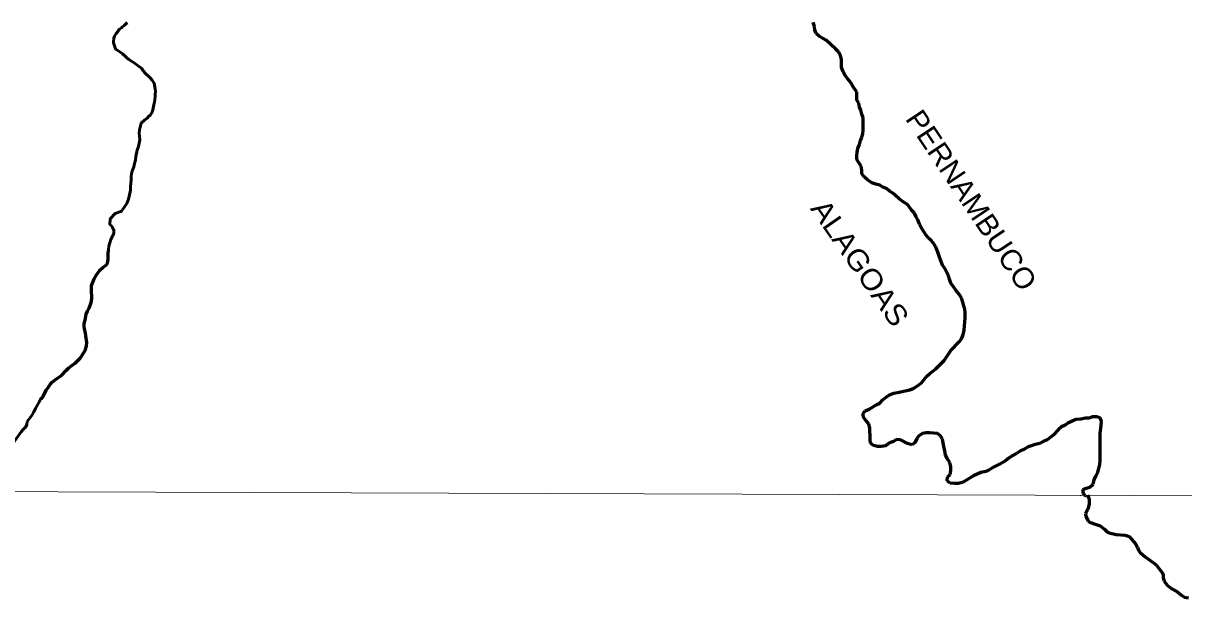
# Model space of a CAD drawing. Extents: x 553962 to 842807, y 8883888 to 9032388.
# Drawn here: x 626649 to 648955, y 9002899 to 9013939 of the extents above; entities that cross this region are included whole.
import ezdxf
from ezdxf.enums import TextEntityAlignment as Align

# ---------------------------------------------------------------- set-up
doc = ezdxf.new("R2010")
doc.units = 0
doc.header["$LTSCALE"] = 150
doc.linetypes.add('LONG_DASH_SHORT_DASH', pattern=[9.9, 6, -1.2, 1.5, -1.2])
for name, color, linetype, lineweight in [('1', 7, 'Continuous', 13), ('24', 7, 'Continuous', 25), ('7', 7, 'LONG_DASH_SHORT_DASH', 60)]:
    doc.layers.add(name, color=color, linetype=linetype, lineweight=lineweight)
doc.layers.add('42', color=7, linetype='Continuous')

msp = doc.modelspace()

# ---------------------------------------------------------------- linework, layer by layer
at = {"layer": '1'}
msp.add_lwpolyline([(565303.2, 9005146.6), (664889.8, 9004806.7), (719872.1, 9004543.9), (790635.8, 9004109)], dxfattribs=at)
for points in [[(646965.9, 9004860.1), (647054.2, 9004901.6), (647053.5, 9004901.6), (647052.8, 9004897.4), (647051.4, 9004891.8), (647051.4, 9004880.6), (647051.4, 9004873.6), (647051.4, 9004869.4), (647051.4, 9004865.2), (647051.4, 9004859.6), (647052.1, 9004852.6), (647052.1, 9004847), (647052.1, 9004842.8), (647052.1, 9004842.1), (647052.1, 9004841.4), (647052.1, 9004840.7), (647052.8, 9004840.7), (647053.5, 9004840.7), (647057.7, 9004841.4), (647061.9, 9004842.1), (647068.9, 9004842.8), (647077.3, 9004843.5), (647085.7, 9004847.7), (647091.3, 9004849.1), (647099.7, 9004853.3), (647109.5, 9004854), (647116.5, 9004858.2), (647123.5, 9004862.4), (647124.9, 9004863.8), (647124.9, 9004868), (647124.9, 9004869.4), (647124.9, 9004870.8), (647124.9, 9004871.5), (647124.9, 9004872.9), (647124.9, 9004874.3), (647124.9, 9004875), (647124.9, 9004875.7), (647124.2, 9004875), (647122.8, 9004873.6), (647122.1, 9004865.2), (647120.7, 9004858.2), (647120, 9004854), (647120, 9004854.7), (647120, 9004855.4), (647120, 9004859.6), (647120, 9004861), (647121.4, 9004862.4), (647122.1, 9004866.6), (647122.1, 9004870.8), (647122.8, 9004876.4), (647122.8, 9004877.8), (647123.5, 9004877.8), (647124.2, 9004877.8), (647124.9, 9004877.8), (647125.6, 9004877.8)], [(647125.6, 9004877.8), (647126.3, 9004877.8), (647125.6, 9004877.8), (647126.3, 9004877.8)]]:
    msp.add_spline(points, degree=3, dxfattribs=at)
at = {"layer": '24', "lineweight": 53}
for points in [[(628385.1, 9013563.7), (628384.6, 9013589.1), (628393.8, 9013653.1), (628406.8, 9013693.5), (628435.3, 9013742.5), (628473.3, 9013786.9), (628489.7, 9013813.2), (628501.5, 9013824.6), (628538.5, 9013852.9), (628556, 9013869.9), (628589.9, 9013894.5), (628628.8, 9013933.2), (628651.1, 9013946.4)], [(628991.5, 9012087.3), (629022.5, 9012108.1), (629071.7, 9012160), (629084.9, 9012162.8), (629086.9, 9012173.2), (629118.1, 9012217.5), (629138.3, 9012273), (629162, 9012369), (629172, 9012423.6), (629184.2, 9012523.3), (629184.4, 9012576), (629190.2, 9012625.9), (629183.6, 9012680.4), (629167.1, 9012786.6), (629159.2, 9012796.9), (629128.4, 9012844.8), (629090.7, 9012887.9), (628980.3, 9012992.9), (628979, 9013000.4), (628970.9, 9013002.3), (628969.2, 9013017.3), (628950.2, 9013031.4), (628929.8, 9013068.9), (628829.8, 9013142.9), (628780.7, 9013176.6), (628727.8, 9013209.3), (628680.6, 9013243), (628636, 9013283.3), (628574.8, 9013335.8), (628552.3, 9013351.7), (628548.7, 9013360.1), (628427, 9013439.7), (628422.5, 9013448.1), (628385.1, 9013563.7)], [(626725, 9006288.4), (626779.1, 9006348.8), (626820, 9006414.7), (626852.1, 9006473.1), (626884.2, 9006537.2), (626914.5, 9006591.8), (626995.8, 9006730.4), (627000.8, 9006736), (627018.2, 9006741.7), (627022, 9006744.6), (627030, 9006769), (627091.7, 9006889.6), (627130.8, 9006942.4), (627168.5, 9006999), (627205.7, 9007042.3), (627264.5, 9007088.6), (627330, 9007129.3), (627383.4, 9007169.9), (627473.6, 9007266.1), (627521.8, 9007311.4), (627580.8, 9007360.5), (627647.4, 9007407.8), (627691, 9007452.1), (627741.2, 9007505), (627838.2, 9007649.2), (627862.8, 9007736.7), (627868.9, 9007802.6), (627855.6, 9007930.4), (627843.1, 9007991.5), (627825.9, 9008062.9), (627820.1, 9008114.6), (627823, 9008171.1), (627839.1, 9008232.2), (627861.6, 9008347.1), (627883.5, 9008403.6), (627919.6, 9008464.8), (627956.3, 9008575), (627969.5, 9008644.6), (627969.3, 9008703.9), (627962.7, 9008772.5), (627963, 9008898.5), (627984.8, 9008964.4), (628013.5, 9009025.6), (628060.6, 9009104.8), (628119, 9009194.3), (628125.3, 9009200.9), (628181.5, 9009242.5), (628249.4, 9009298.2), (628267.2, 9009335.9), (628279.4, 9009398.9), (628279.5, 9009462.9), (628282.4, 9009525), (628295.3, 9009656.7), (628310.9, 9009719.8), (628332.7, 9009781.9), (628390, 9009900.6), (628393.8, 9009911.9), (628393.7, 9009960.8), (628392.5, 9009967.4), (628378, 9009983.3), (628365.8, 9010017.1), (628342.8, 9010045.3), (628316.9, 9010072.4), (628323, 9010177.8), (628415.6, 9010283.4), (628526.3, 9010323.3), (628535.7, 9010328), (628642.2, 9010476), (628665.7, 9010541), (628685.1, 9010606.9), (628709.8, 9010732.1), (628710.2, 9010799.8), (628722.3, 9010925.8), (628722.4, 9010990.7), (628731.8, 9011054.7), (628747.3, 9011116.8), (628773, 9011182.8), (628789.2, 9011246.8), (628807.6, 9011309.8), (628814.8, 9011376.6), (628839.2, 9011499.9), (628862, 9011567.7), (628878.5, 9011635.5), (628887.4, 9011699.5), (628887.1, 9011760.6), (628880.7, 9011826.4), (628881.1, 9011890.3), (628917.2, 9012018.4), (628991.5, 9012087.3)], [(626161, 9005249.2), (626188.6, 9005351.8), (626211.6, 9005488.2), (626262, 9005622), (626290.8, 9005686), (626318.1, 9005740.6), (626357.2, 9005784), (626440.5, 9005861.4), (626481.1, 9005905.8), (626516.3, 9005951), (626547.5, 9005998.1), (626576.5, 9006046.2), (626606.6, 9006087.7), (626651.3, 9006133.9), (626697.2, 9006185.8), (626721.1, 9006227.2), (626725, 9006288.4)]]:
    msp.add_lwpolyline(points, dxfattribs=at)
at = {"layer": '7'}
for points in [[(642587.9, 9012738.2), (642555, 9012803.3), (642491.9, 9012875.8), (642449, 9012935.9), (642411, 9013003.5), (642378, 9013091.2), (642377.5, 9013241.9), (642359.6, 9013319.6), (642321.7, 9013387.2), (642261.2, 9013447.2), (642084.7, 9013614.7), (642014.2, 9013649.5), (641953.8, 9013686.9), (641888.2, 9013741.9), (641865.4, 9013807), (641855.1, 9013874.8), (641829.7, 9013952.5)], [(642956.5, 9010871.9), (642875.9, 9010931.8), (642812.9, 9010989.2), (642767.5, 9011046.8), (642764.7, 9011117.1), (642756.9, 9011189.8), (642714, 9011252.4), (642671, 9011320), (642668.2, 9011392.8), (642675.5, 9011460.6), (642692.8, 9011531), (642720.2, 9011611.5), (642740, 9011684.4), (642767.4, 9011749.8), (642787.2, 9011815.1), (642792, 9011885.4), (642791.1, 9012118.9), (642768.3, 9012191.6), (642750.4, 9012266.9), (642720, 9012329.5), (642709.7, 9012402.3), (642674.3, 9012462.4), (642669, 9012537.7), (642668.7, 9012615.5), (642587.9, 9012738.2)], [(642909.8, 9006525.4), (642972.5, 9006563.4), (643042.7, 9006603.9), (643110.4, 9006636.8), (643173, 9006699.9), (643233.1, 9006755.4), (643300.8, 9006800.9), (643383.6, 9006828.9), (643451.3, 9006846.8), (643689.8, 9006898), (643767.6, 9006926), (643840.3, 9006969), (643907.9, 9007024.6), (643960.5, 9007085.1), (644013, 9007153.1), (644073.1, 9007208.6), (644128.2, 9007249), (644188.3, 9007299.5), (644348.5, 9007460.9), (644480.9, 9007652.3), (644638.6, 9007816.2), (644681, 9007874.2), (644715.9, 9007949.6), (644735.7, 9008040.1), (644740.4, 9008123), (644752.4, 9008281.2), (644752, 9008371.6), (644749.2, 9008446.9), (644726.4, 9008512.1), (644706.1, 9008577.3), (644685.6, 9008662.5), (644630.1, 9008742.6), (644574.6, 9008810.2), (644531.6, 9008875.3), (644478.6, 9008945.3), (644453.2, 9009020.6), (644432.8, 9009088.2), (644394.9, 9009160.9), (644364.5, 9009226), (644319, 9009288.6), (644283.6, 9009373.8), (644253.1, 9009461.5), (644230.2, 9009539.3), (644192.1, 9009634.5), (644149.2, 9009702.1), (644098.7, 9009762.2), (644045.8, 9009812.1), (643997.8, 9009874.7), (643906.8, 9010017.4), (643876.5, 9010080), (643846, 9010160.2), (643810.6, 9010220.3), (643780.2, 9010290.5), (643729.8, 9010343), (643646.4, 9010458.1), (643563.3, 9010510.5), (643485.3, 9010562.9), (643417.2, 9010627.8), (643364.3, 9010672.8), (643296.3, 9010710.2), (643238.3, 9010762.6), (643170.4, 9010790), (643112.5, 9010829.9), (643034.5, 9010844.6), (642956.5, 9010871.9)], [(626960, 9006669.3), (626995.8, 9006730.4), (627000.8, 9006736), (627018.2, 9006741.7), (627022, 9006744.6), (627030, 9006769), (627091.7, 9006889.6), (627130.8, 9006942.4), (627168.5, 9006999), (627205.7, 9007042.3), (627264.5, 9007088.6), (627330, 9007129.3), (627383.4, 9007169.9), (627473.6, 9007266.1), (627521.8, 9007311.4), (627580.8, 9007360.5), (627647.4, 9007407.8), (627691, 9007452.1), (627741.2, 9007505), (627838.2, 9007649.2), (627862.8, 9007736.7), (627868.9, 9007802.6), (627855.6, 9007930.4), (627843.1, 9007991.5), (627825.9, 9008062.9), (627820.1, 9008114.6), (627823, 9008171.1), (627839.1, 9008232.2), (627861.6, 9008347.1), (627883.5, 9008403.6), (627919.6, 9008464.8), (627956.3, 9008575), (627969.5, 9008644.6), (627969.3, 9008703.9), (627962.7, 9008772.5), (627963, 9008898.5), (627984.8, 9008964.4), (628013.5, 9009025.6), (628060.6, 9009104.8), (628119, 9009194.3), (628125.3, 9009200.9), (628181.5, 9009242.5), (628249.4, 9009298.2), (628267.2, 9009335.9), (628279.4, 9009398.9), (628279.5, 9009462.9), (628282.4, 9009525), (628286.6, 9009568.2)], [(644220.5, 9006056.8), (644074.8, 9006071.2), (644001.9, 9006068.3), (643934.1, 9006053), (643864, 9006012.5), (643821.4, 9005959.6), (643789.1, 9005879.1), (643726.4, 9005838.6), (643645.9, 9005865.8), (643512.5, 9005935.6), (643434.6, 9005937.7), (643374.4, 9005902.3), (643301.7, 9005876.9), (643231.5, 9005821.3), (643141.2, 9005805.8), (643070.8, 9005805.5), (642992.8, 9005822.7), (642932.4, 9005870.2), (642927.1, 9005938), (642924.3, 9006023.3), (642924, 9006093.6), (642921.2, 9006161.4), (642900.9, 9006239.2), (642847.9, 9006296.7), (642805, 9006354.2), (642787.1, 9006434.5), (642834.6, 9006492.5), (642909.8, 9006525.4)], [(647062.3, 9004859.8), (647025.9, 9004904.3), (647013.1, 9004977.1), (647078.3, 9005005), (647151.1, 9005022.9), (647211.2, 9005080.9), (647230.9, 9005163.9), (647263.3, 9005239.3), (647305.7, 9005314.9), (647325.6, 9005382.8), (647340.4, 9005460.7), (647345.1, 9005536), (647349.6, 9005686.7), (647348.2, 9006058.2), (647370.2, 9006219), (647374.9, 9006286.8), (647347, 9006357), (647279.1, 9006376.8), (647201.3, 9006376.5), (647136, 9006353.6), (647063.2, 9006350.7), (646977.9, 9006332.8), (646882.5, 9006322.3), (646794.7, 9006286.8), (646729.5, 9006256.3), (646676.9, 9006213.4), (646604.1, 9006183), (646549, 9006135), (646446.5, 9006026.6), (646386.3, 9005976.1), (646331.2, 9005935.7), (646266, 9005907.8), (646190.8, 9005864.7), (646098, 9005846.7), (645962.5, 9005800.9), (645879.8, 9005750.3), (645814.5, 9005722.4), (645739.3, 9005674.4), (645666.7, 9005633.9), (645599, 9005588.4), (645528.9, 9005532.8), (645448.7, 9005484.8), (645288.2, 9005403.7), (645230.5, 9005363.3), (645150.3, 9005327.8), (645057.4, 9005307.2), (644911.9, 9005243.8), (644769.1, 9005152.8), (644701.4, 9005117.3), (644621.1, 9005096.9), (644548.2, 9005094), (644465.3, 9005103.7), (644409.8, 9005143.6), (644412.1, 9005221.5), (644464.7, 9005269.4), (644479.5, 9005342.3), (644479.2, 9005417.6), (644458.8, 9005497.9), (644408.2, 9005575.5), (644377.8, 9005648.2), (644360, 9005720.9), (644342.1, 9005803.7), (644318.9, 9005944.2), (644281, 9006014.3), (644220.5, 9006056.8)], [(647102.1, 9004868.2), (647133.8, 9004797.4), (647139.7, 9004697.7), (647112.7, 9004599.3), (647071.4, 9004533.6), (647065.5, 9004510.9), (647070.2, 9004465.4), (647114.8, 9004372.7), (647145.9, 9004353.5), (647287.9, 9004301.4)], [(647287.9, 9004301.4), (647349.8, 9004278.7), (647428.9, 9004220), (647491, 9004161.7), (647523.9, 9004147.1), (647653.6, 9004116.9), (647828.8, 9004104.7), (647906.2, 9004077.1), (648025, 9003938.3), (648068.8, 9003867.8), (648090.9, 9003802.8), (648115.2, 9003770.7), (648211.5, 9003685.2), (648303.2, 9003619.5)], [(648303.2, 9003619.5), (648427.5, 9003530.4), (648554.2, 9003368.9), (648558.1, 9003321.1)], [(648558.1, 9003321.1), (648561.3, 9003280.6), (648575.3, 9003215.5), (648643.2, 9003134.5), (648724.5, 9003072), (648834.8, 9003014.8), (648910.7, 9002950.7), (648970.7, 9002913.9), (649048, 9002899.4)]]:
    msp.add_lwpolyline(points, dxfattribs=at)

# ---------------------------------------------------------------- texts
at = {"layer": '42'}
for s, rotation, width, p in [('PERNAMBUCO', 303.725, 1.05, (644707.5, 9010428)), ('ALAGOAS', 304.834, 1.1, (642567.7, 9009221.7))]:
    msp.add_text(s, height=400, rotation=rotation, dxfattribs=dict(at, width=width)).set_placement(p, align=Align.CENTER)

doc.saveas('drawing.dxf')
